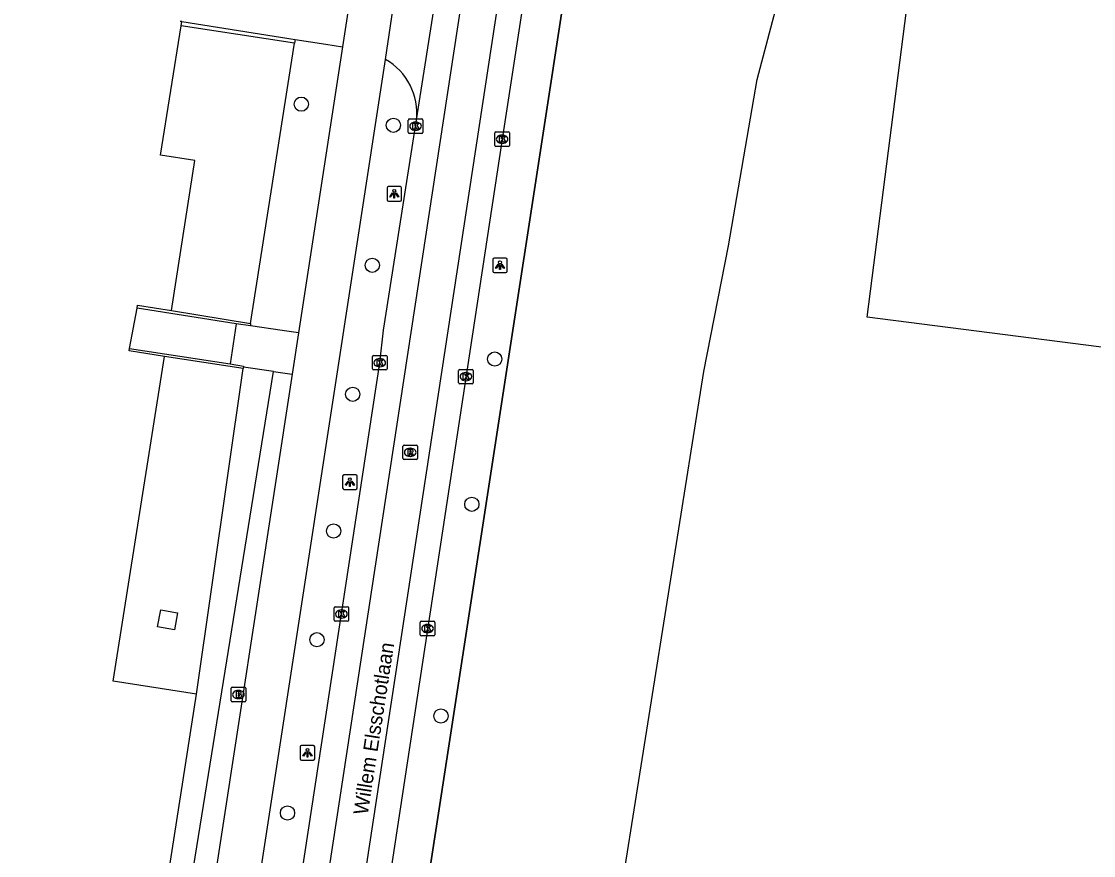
# Model space of a CAD drawing. Extents: x 161094 to 161705, y 379509 to 380907.
# Drawn here: x 161340 to 161413.8, y 380617.3 to 380674.7 of the extents above; entities that cross this region are included whole.
import ezdxf

# ---------------------------------------------------------------- set-up
doc = ezdxf.new("R2010")
doc.units = 0
for name, color, linetype in [('IMGEO_Boom', 7, 'Continuous'), ('IMGEO_Brandkraan', 7, 'Continuous'), ('IMGEO_Fietspad_gesloten', 7, 'Continuous'), ('IMGEO_Grasland_overig', 7, 'Continuous'), ('IMGEO_Groenvoorziening', 7, 'Continuous'), ('IMGEO_Haag', 7, 'Continuous'), ('IMGEO_Hek', 7, 'Continuous'), ('IMGEO_Kolk', 7, 'Continuous'), ('IMGEO_Lichtpunt', 7, 'Continuous'), ('IMGEO_Muur', 7, 'Continuous'), ('IMGEO_Openbare_ruimte_label', 7, 'Continuous'), ('IMGEO_Pand', 7, 'Continuous'), ('IMGEO_Pand_vergunning_verleend', 7, 'Continuous'), ('IMGEO_Rijbaan_lokaal_gesloten', 7, 'Continuous'), ('IMGEO_Rioolput', 7, 'Continuous'), ('IMGEO_Voetpad_open', 7, 'Continuous')]:
    doc.layers.add(name, color=color, linetype=linetype)

msp = doc.modelspace()

# ---------------------------------------------------------------- linework, layer by layer
at = {"layer": 'IMGEO_Boom'}
for centre in [(161359.244, 380668.971), (161365.582, 380667.515), (161364.131, 380657.886), (161372.554, 380651.434), (161362.782, 380649.011), (161370.978, 380641.442), (161361.467, 380639.604), (161360.319, 380632.127), (161368.856, 380626.877), (161358.295, 380620.204)]:
    msp.add_circle(centre, 0.489, dxfattribs=at)
at = {"layer": 'IMGEO_Brandkraan'}
for p, q in [((161354.415, 380627.93), (161354.415, 380628.782)), ((161354.49, 380628.856), (161355.342, 380628.856)), ((161354.903, 380628.636), (161354.928, 380628.636)), ((161355.416, 380628.782), (161355.416, 380627.93)), ((161355.342, 380627.856), (161354.49, 380627.856)), ((161354.926, 380628.076), (161354.901, 380628.076))]:
    msp.add_line(p, q, dxfattribs=at)
for points in [[(161354.415, 380627.93), (161354.415, 380628.782)], [(161354.49, 380628.856), (161355.342, 380628.856)], [(161354.763, 380628.556), (161354.763, 380628.156), (161354.976, 380628.156)], [(161354.994, 380628.556), (161354.763, 380628.556)], [(161354.942, 380628.475), (161354.888, 380628.475), (161354.888, 380628.399)], [(161354.888, 380628.399), (161354.941, 380628.399)], [(161354.95, 380628.323), (161354.888, 380628.323), (161354.888, 380628.242)], [(161354.888, 380628.242), (161354.95, 380628.242)], [(161355.416, 380628.782), (161355.416, 380627.93)], [(161355.342, 380627.856), (161354.49, 380627.856)]]:
    msp.add_lwpolyline(points, dxfattribs=at)
for centre, radius, start, end in [((161354.492, 380628.78), 0.0765, 91.55205, 178.44795), ((161354.492, 380628.78), 0.0765, 91.55205, 178.44795), ((161354.943, 380628.437), 0.0379, 267.82845, 90.93552), ((161354.951, 380628.282), 0.0404, 269.87594, 90.50774), ((161354.998, 380628.411), 0.145, 59.4692, 91.53667), ((161355.023, 380628.458), 0.0922, 285.51372, 58.15012), ((161355.028, 380628.266), 0.105, 301.31148, 78.98903), ((161355.34, 380628.78), 0.0765, 1.55205, 88.44795), ((161355.34, 380628.78), 0.0765, 1.55205, 88.44795), ((161354.492, 380627.932), 0.0765, 181.55205, 268.44795), ((161354.492, 380627.932), 0.0765, 181.55205, 268.44795), ((161354.982, 380628.407), 0.251, 268.66757, 293.53466), ((161355.34, 380627.932), 0.0765, 271.55205, 358.44795), ((161355.34, 380627.932), 0.0765, 271.55205, 358.44795)]:
    msp.add_arc(centre, radius, start, end, dxfattribs=at)
for centre, major_axis, ratio, start_param, end_param in [((161354.902, 380628.356), (-0.387, 0.002), 0.722429, 4.712389, 7.853982), ((161354.927, 380628.356), (-0.39, 0.002), 0.717154, 1.570796, 4.712389)]:
    msp.add_ellipse(centre, major_axis=major_axis, ratio=ratio, start_param=start_param, end_param=end_param, dxfattribs=at)
at = {"layer": 'IMGEO_Fietspad_gesloten'}
for points in [[(161362.964, 380678.743), (161362.07, 380672.915)], [(161365.033, 380672.035), (161366.062, 380679.022)], [(161362.07, 380672.915), (161359.052, 380653.248)], [(161347.54, 380558.203), (161365.033, 380672.035)], [(161359.052, 380653.248), (161358.615, 380650.395)], [(161358.615, 380650.395), (161352.499, 380610.536)]]:
    msp.add_lwpolyline(points, dxfattribs=at)
at = {"layer": 'IMGEO_Grasland_overig'}
msp.add_lwpolyline([(161380.532, 380610.266), (161380.816, 380612.046), (161386.952, 380650.576), (161388.642, 380659.221), (161390.629, 380670.674), (161392.829, 380679.019), (161394.81, 380684.162), (161399.827, 380694.406), (161401.55, 380696.729), (161411.895, 380689.797), (161413.736, 380691.575), (161412.517, 380710.46)], dxfattribs=at)
at = {"layer": 'IMGEO_Groenvoorziening'}
for points in [[(161405.29, 380858.44), (161376.121, 380668.459), (161366.925, 380608.735), (161353.592, 380520.726), (161347.606, 380481.216)], [(161355.744, 380653.874), (161358.768, 380673.154)], [(161350.731, 380633.977), (161350.52, 380632.797), (161349.358, 380633.011), (161349.569, 380634.173), (161350.731, 380633.977)]]:
    msp.add_lwpolyline(points, dxfattribs=at)
at = {"layer": 'IMGEO_Haag'}
for points in [[(161350.91, 380610.77), (161357.34, 380650.575)], [(161352.038, 380628.383), (161355.234, 380650.781)]]:
    msp.add_lwpolyline(points, dxfattribs=at)
at = {"layer": 'IMGEO_Hek'}
for points in [[(161376.121, 380668.459), (161405.29, 380858.44)], [(161353.592, 380520.726), (161366.925, 380608.735), (161376.121, 380668.459)]]:
    msp.add_lwpolyline(points, dxfattribs=at)
at = {"layer": 'IMGEO_Kolk'}
for p, q in [((161366.61, 380667.026), (161366.61, 380667.878)), ((161366.685, 380667.952), (161367.537, 380667.952)), ((161367.098, 380667.732), (161367.123, 380667.732)), ((161367.611, 380667.878), (161367.611, 380667.026)), ((161367.537, 380666.952), (161366.685, 380666.952)), ((161367.121, 380667.172), (161367.096, 380667.172)), ((161372.564, 380666.133), (161372.564, 380666.985)), ((161372.639, 380667.059), (161373.491, 380667.059)), ((161373.052, 380666.839), (161373.077, 380666.839)), ((161373.565, 380666.985), (161373.565, 380666.133)), ((161373.491, 380666.059), (161372.639, 380666.059)), ((161373.075, 380666.279), (161373.05, 380666.279)), ((161364.142, 380650.756), (161364.142, 380651.608)), ((161364.217, 380651.682), (161365.069, 380651.682)), ((161364.63, 380651.462), (161364.655, 380651.462)), ((161365.143, 380651.608), (161365.143, 380650.756)), ((161365.069, 380650.682), (161364.217, 380650.682)), ((161364.653, 380650.902), (161364.628, 380650.902)), ((161370.074, 380649.798), (161370.074, 380650.65)), ((161370.149, 380650.724), (161371.001, 380650.724)), ((161370.562, 380650.504), (161370.587, 380650.504)), ((161371.075, 380650.65), (161371.075, 380649.798)), ((161371.001, 380649.724), (161370.149, 380649.724)), ((161370.585, 380649.944), (161370.56, 380649.944)), ((161361.503, 380633.469), (161361.503, 380634.321)), ((161361.578, 380634.395), (161362.43, 380634.395)), ((161361.991, 380634.175), (161362.016, 380634.175)), ((161362.504, 380634.321), (161362.504, 380633.469)), ((161362.014, 380633.615), (161361.989, 380633.615)), ((161362.43, 380633.395), (161361.578, 380633.395)), ((161367.433, 380632.467), (161367.433, 380633.319)), ((161367.508, 380633.393), (161368.36, 380633.393)), ((161367.921, 380633.173), (161367.946, 380633.173)), ((161368.434, 380633.319), (161368.434, 380632.467)), ((161368.36, 380632.393), (161367.508, 380632.393)), ((161367.944, 380632.613), (161367.919, 380632.613))]:
    msp.add_line(p, q, dxfattribs=at)
for points in [[(161366.61, 380667.026), (161366.61, 380667.878)], [(161366.685, 380667.952), (161367.537, 380667.952)], [(161366.931, 380667.652), (161367.054, 380667.652), (161367.054, 380667.501), (161367.184, 380667.652), (161367.348, 380667.652), (161367.202, 380667.501), (161367.355, 380667.252), (161367.203, 380667.252), (161367.118, 380667.416), (161367.054, 380667.349), (161367.054, 380667.252), (161366.931, 380667.252), (161366.931, 380667.652)], [(161367.611, 380667.878), (161367.611, 380667.026)], [(161367.537, 380666.952), (161366.685, 380666.952)], [(161372.564, 380666.133), (161372.564, 380666.985)], [(161372.639, 380667.059), (161373.491, 380667.059)], [(161372.885, 380666.759), (161373.008, 380666.759), (161373.008, 380666.608), (161373.138, 380666.759), (161373.302, 380666.759), (161373.156, 380666.608), (161373.309, 380666.359), (161373.157, 380666.359), (161373.072, 380666.523), (161373.008, 380666.456), (161373.008, 380666.359), (161372.885, 380666.359), (161372.885, 380666.759)], [(161373.565, 380666.985), (161373.565, 380666.133)], [(161373.491, 380666.059), (161372.639, 380666.059)], [(161364.142, 380650.756), (161364.142, 380651.608)], [(161364.217, 380651.682), (161365.069, 380651.682)], [(161364.463, 380651.382), (161364.586, 380651.382), (161364.586, 380651.231), (161364.716, 380651.382), (161364.88, 380651.382), (161364.734, 380651.231), (161364.887, 380650.982), (161364.735, 380650.982), (161364.65, 380651.146), (161364.586, 380651.079), (161364.586, 380650.982), (161364.463, 380650.982), (161364.463, 380651.382)], [(161365.143, 380651.608), (161365.143, 380650.756)], [(161365.069, 380650.682), (161364.217, 380650.682)], [(161370.074, 380649.798), (161370.074, 380650.65)], [(161370.149, 380650.724), (161371.001, 380650.724)], [(161370.395, 380650.424), (161370.518, 380650.424), (161370.518, 380650.273), (161370.648, 380650.424), (161370.812, 380650.424), (161370.666, 380650.273), (161370.819, 380650.024), (161370.667, 380650.024), (161370.582, 380650.188), (161370.518, 380650.121), (161370.518, 380650.024), (161370.395, 380650.024), (161370.395, 380650.424)], [(161371.075, 380650.65), (161371.075, 380649.798)], [(161371.001, 380649.724), (161370.149, 380649.724)], [(161361.503, 380633.469), (161361.503, 380634.321)], [(161361.578, 380634.395), (161362.43, 380634.395)], [(161362.504, 380634.321), (161362.504, 380633.469)], [(161361.824, 380634.095), (161361.947, 380634.095), (161361.947, 380633.944), (161362.077, 380634.095), (161362.241, 380634.095), (161362.095, 380633.944), (161362.248, 380633.695), (161362.096, 380633.695), (161362.011, 380633.859), (161361.947, 380633.792), (161361.947, 380633.695), (161361.824, 380633.695), (161361.824, 380634.095)], [(161362.43, 380633.395), (161361.578, 380633.395)], [(161367.433, 380632.467), (161367.433, 380633.319)], [(161367.508, 380633.393), (161368.36, 380633.393)], [(161367.754, 380633.093), (161367.877, 380633.093), (161367.877, 380632.942), (161368.007, 380633.093), (161368.171, 380633.093), (161368.025, 380632.942), (161368.178, 380632.693), (161368.026, 380632.693), (161367.941, 380632.857), (161367.877, 380632.79), (161367.877, 380632.693), (161367.754, 380632.693), (161367.754, 380633.093)], [(161368.434, 380633.319), (161368.434, 380632.467)], [(161368.36, 380632.393), (161367.508, 380632.393)]]:
    msp.add_lwpolyline(points, dxfattribs=at)
for centre, start, end in [((161366.687, 380667.876), 91.55205, 178.44795), ((161366.687, 380667.876), 91.55205, 178.44795), ((161367.535, 380667.876), 1.55205, 88.44795), ((161367.535, 380667.876), 1.55205, 88.44795), ((161366.687, 380667.028), 181.55205, 268.44795), ((161366.687, 380667.028), 181.55205, 268.44795), ((161367.535, 380667.028), 271.55205, 358.44795), ((161367.535, 380667.028), 271.55205, 358.44795), ((161372.641, 380666.983), 91.55205, 178.44795), ((161372.641, 380666.983), 91.55205, 178.44795), ((161373.489, 380666.983), 1.55205, 88.44795), ((161373.489, 380666.983), 1.55205, 88.44795), ((161372.641, 380666.135), 181.55205, 268.44795), ((161372.641, 380666.135), 181.55205, 268.44795), ((161373.489, 380666.135), 271.55205, 358.44795), ((161373.489, 380666.135), 271.55205, 358.44795), ((161364.219, 380651.606), 91.55205, 178.44795), ((161364.219, 380651.606), 91.55205, 178.44795), ((161365.067, 380651.606), 1.55205, 88.44795), ((161365.067, 380651.606), 1.55205, 88.44795), ((161364.219, 380650.758), 181.55205, 268.44795), ((161364.219, 380650.758), 181.55205, 268.44795), ((161365.067, 380650.758), 271.55205, 358.44795), ((161365.067, 380650.758), 271.55205, 358.44795), ((161370.151, 380650.648), 91.55205, 178.44795), ((161370.151, 380650.648), 91.55205, 178.44795), ((161370.999, 380650.648), 1.55205, 88.44795), ((161370.999, 380650.648), 1.55205, 88.44795), ((161370.151, 380649.8), 181.55205, 268.44795), ((161370.151, 380649.8), 181.55205, 268.44795), ((161370.999, 380649.8), 271.55205, 358.44795), ((161370.999, 380649.8), 271.55205, 358.44795), ((161361.58, 380634.319), 91.55205, 178.44795), ((161361.58, 380634.319), 91.55205, 178.44795), ((161362.428, 380634.319), 1.55205, 88.44795), ((161362.428, 380634.319), 1.55205, 88.44795), ((161361.58, 380633.471), 181.55205, 268.44795), ((161361.58, 380633.471), 181.55205, 268.44795), ((161362.428, 380633.471), 271.55205, 358.44795), ((161362.428, 380633.471), 271.55205, 358.44795), ((161367.51, 380633.317), 91.55205, 178.44795), ((161367.51, 380633.317), 91.55205, 178.44795), ((161368.358, 380633.317), 1.55205, 88.44795), ((161368.358, 380633.317), 1.55205, 88.44795), ((161367.51, 380632.469), 181.55205, 268.44795), ((161367.51, 380632.469), 181.55205, 268.44795), ((161368.358, 380632.469), 271.55205, 358.44795), ((161368.358, 380632.469), 271.55205, 358.44795)]:
    msp.add_arc(centre, 0.0765, start, end, dxfattribs=at)
for centre, major_axis, ratio, start_param, end_param in [((161367.097, 380667.452), (-0.387, 0.002), 0.722429, 4.712389, 7.853982), ((161367.122, 380667.452), (-0.39, 0.002), 0.717154, 1.570796, 4.712389), ((161373.051, 380666.559), (-0.387, 0.002), 0.722429, 4.712389, 7.853982), ((161373.076, 380666.559), (-0.39, 0.002), 0.717154, 1.570796, 4.712389), ((161364.629, 380651.182), (-0.387, 0.002), 0.722429, 4.712389, 7.853982), ((161364.654, 380651.182), (-0.39, 0.002), 0.717154, 1.570796, 4.712389), ((161370.561, 380650.224), (-0.387, 0.002), 0.722429, 4.712389, 7.853982), ((161370.586, 380650.224), (-0.39, 0.002), 0.717154, 1.570796, 4.712389), ((161361.99, 380633.895), (-0.387, 0.002), 0.722429, 4.712389, 7.853982), ((161362.015, 380633.895), (-0.39, 0.002), 0.717154, 1.570796, 4.712389), ((161367.92, 380632.893), (-0.387, 0.002), 0.722429, 4.712389, 7.853982), ((161367.945, 380632.893), (-0.39, 0.002), 0.717154, 1.570796, 4.712389)]:
    msp.add_ellipse(centre, major_axis=major_axis, ratio=ratio, start_param=start_param, end_param=end_param, dxfattribs=at)
at = {"layer": 'IMGEO_Lichtpunt'}
for p, q in [((161365.144, 380663.201), (161365.144, 380662.394)), ((161365.144, 380663.201), (161365.144, 380662.394)), ((161366.046, 380663.296), (161365.238, 380663.296)), ((161366.046, 380663.296), (161365.238, 380663.296)), ((161366.14, 380662.394), (161366.14, 380663.201)), ((161366.14, 380662.394), (161366.14, 380663.201)), ((161365.238, 380662.3), (161366.046, 380662.3)), ((161365.238, 380662.3), (161366.046, 380662.3)), ((161372.42, 380658.29), (161372.42, 380657.483)), ((161372.42, 380658.29), (161372.42, 380657.483)), ((161373.322, 380658.385), (161372.514, 380658.385)), ((161373.322, 380658.385), (161372.514, 380658.385)), ((161373.416, 380657.483), (161373.416, 380658.29)), ((161373.416, 380657.483), (161373.416, 380658.29)), ((161372.514, 380657.389), (161373.322, 380657.389)), ((161372.514, 380657.389), (161373.322, 380657.389)), ((161362.088, 380643.372), (161362.088, 380642.565)), ((161362.088, 380643.372), (161362.088, 380642.565)), ((161362.99, 380643.467), (161362.182, 380643.467)), ((161362.99, 380643.467), (161362.182, 380643.467)), ((161363.084, 380642.565), (161363.084, 380643.372)), ((161363.084, 380642.565), (161363.084, 380643.372)), ((161362.182, 380642.471), (161362.99, 380642.471)), ((161362.182, 380642.471), (161362.99, 380642.471)), ((161359.172, 380624.748), (161359.172, 380623.941)), ((161359.172, 380624.748), (161359.172, 380623.941)), ((161360.074, 380624.843), (161359.266, 380624.843)), ((161360.074, 380624.843), (161359.266, 380624.843)), ((161360.168, 380623.941), (161360.168, 380624.748)), ((161360.168, 380623.941), (161360.168, 380624.748)), ((161359.266, 380623.847), (161360.074, 380623.847)), ((161359.266, 380623.847), (161360.074, 380623.847))]:
    msp.add_line(p, q, dxfattribs=at)
for points in [[(161365.518, 380662.865), (161365.557, 380662.837), (161365.369, 380662.575), (161365.331, 380662.602), (161365.518, 380662.865)], [(161365.62, 380662.817), (161365.667, 380662.817), (161365.667, 380662.495), (161365.62, 380662.495), (161365.62, 380662.817)], [(161365.73, 380662.837), (161365.768, 380662.864), (161365.955, 380662.602), (161365.916, 380662.574), (161365.73, 380662.837)], [(161372.794, 380657.954), (161372.833, 380657.926), (161372.645, 380657.664), (161372.607, 380657.691), (161372.794, 380657.954)], [(161372.896, 380657.906), (161372.943, 380657.906), (161372.943, 380657.584), (161372.896, 380657.584), (161372.896, 380657.906)], [(161373.006, 380657.926), (161373.044, 380657.953), (161373.231, 380657.691), (161373.192, 380657.663), (161373.006, 380657.926)], [(161362.462, 380643.036), (161362.501, 380643.008), (161362.313, 380642.746), (161362.275, 380642.773), (161362.462, 380643.036)], [(161362.674, 380643.008), (161362.712, 380643.035), (161362.899, 380642.773), (161362.86, 380642.745), (161362.674, 380643.008)], [(161362.564, 380642.988), (161362.611, 380642.988), (161362.611, 380642.666), (161362.564, 380642.666), (161362.564, 380642.988)], [(161359.546, 380624.412), (161359.585, 380624.384), (161359.397, 380624.122), (161359.359, 380624.149), (161359.546, 380624.412)], [(161359.648, 380624.364), (161359.695, 380624.364), (161359.695, 380624.042), (161359.648, 380624.042), (161359.648, 380624.364)], [(161359.758, 380624.384), (161359.796, 380624.411), (161359.983, 380624.149), (161359.944, 380624.121), (161359.758, 380624.384)]]:
    msp.add_lwpolyline(points, dxfattribs=at)
for centre in [(161365.643, 380662.999), (161372.919, 380658.088), (161362.587, 380643.17), (161359.671, 380624.546)]:
    msp.add_circle(centre, 0.0994, dxfattribs=at)
for centre, start, end in [((161365.238, 380663.201), 90, 180), ((161365.238, 380663.201), 90, 180), ((161366.046, 380663.201), 0, 90), ((161366.046, 380663.201), 0, 90), ((161365.238, 380662.394), 180, 270), ((161365.238, 380662.394), 180, 270), ((161366.046, 380662.394), 270, 0), ((161366.046, 380662.394), 270, 360), ((161372.514, 380658.29), 90, 180), ((161372.514, 380658.29), 90, 180), ((161373.322, 380658.29), 0, 90), ((161373.322, 380658.29), 0, 90), ((161372.514, 380657.483), 180, 270), ((161372.514, 380657.483), 180, 270), ((161373.322, 380657.483), 270, 0), ((161373.322, 380657.483), 270, 360), ((161362.182, 380643.372), 90, 180), ((161362.182, 380643.372), 90, 180), ((161362.99, 380643.372), 0, 90), ((161362.99, 380643.372), 0, 90), ((161362.182, 380642.565), 180, 270), ((161362.182, 380642.565), 180, 270), ((161362.99, 380642.565), 270, 0), ((161362.99, 380642.565), 270, 360), ((161359.266, 380624.748), 90, 180), ((161359.266, 380624.748), 90, 180), ((161360.074, 380624.748), 0, 90), ((161360.074, 380624.748), 0, 90), ((161359.266, 380623.941), 180, 270), ((161359.266, 380623.941), 180, 270), ((161360.074, 380623.941), 270, 0), ((161360.074, 380623.941), 270, 360)]:
    msp.add_arc(centre, 0.0946, start, end, dxfattribs=at)
at = {"layer": 'IMGEO_Muur'}
for points in [[(161358.768, 380673.154), (161350.974, 380674.355)], [(161351.021, 380674.65), (161358.821, 380673.421)], [(161358.821, 380673.421), (161358.768, 380673.154)], [(161354.752, 380653.867), (161347.94, 380654.933)], [(161350.309, 380654.767), (161355.744, 380653.874)], [(161355.744, 380653.715), (161354.752, 380653.867)], [(161355.744, 380653.874), (161355.744, 380653.715)], [(161347.42, 380652.158), (161354.34, 380651.099)], [(161355.234, 380650.781), (161349.821, 380651.619)], [(161354.34, 380651.099), (161355.271, 380650.933), (161355.268, 380650.867)], [(161355.268, 380650.867), (161355.234, 380650.781)]]:
    msp.add_lwpolyline(points, dxfattribs=at)
at = {"layer": 'IMGEO_Pand'}
for points in [[(161350.309, 380654.767), (161351.908, 380665.091), (161349.549, 380665.469), (161350.974, 380674.355)], [(161351.021, 380674.65), (161350.918, 380674.666)], [(161350.974, 380674.355), (161351.021, 380674.65)], [(161347.42, 380652.158), (161347.94, 380654.933)], [(161347.94, 380654.933), (161347.981, 380655.15), (161350.309, 380654.767)], [(161349.821, 380651.619), (161347.389, 380651.995), (161347.42, 380652.158)], [(161352.038, 380628.383), (161346.301, 380629.278), (161349.821, 380651.619)], [(161349.332, 380611.003), (161352.038, 380628.383)]]:
    msp.add_lwpolyline(points, dxfattribs=at)
at = {"layer": 'IMGEO_Pand_vergunning_verleend'}
msp.add_lwpolyline([(161398.18, 380654.32), (161402.454, 380687.597), (161464.781, 380678.671), (161460.613, 380646.22), (161432.685, 380649.806), (161433.004, 380652.29), (161426.809, 380653.085), (161426.501, 380650.683), (161398.18, 380654.32)], dxfattribs=at)
at = {"layer": 'IMGEO_Rijbaan_lokaal_gesloten'}
for points in [[(161339.984, 380477.773), (161375.194, 380708.235), (161388.922, 380797.51), (161396.234, 380843.996), (161396.663, 380846.991)], [(161399.153, 380846.596), (161398.722, 380843.492), (161391.386, 380797.079), (161377.702, 380708.239), (161342.463, 380477.394)], [(161400.962, 380846.207), (161400.622, 380844.851), (161395.87, 380814.342), (161392.957, 380796.042), (161379.164, 380706.261), (161373.065, 380666.559), (161354.682, 380545.949), (161344.875, 380482.113)], [(161367.178, 380667.879), (161369.527, 380682.914)], [(161351.073, 380562.281), (161364.643, 380651.182), (161364.91, 380653.432), (161367.178, 380667.879)]]:
    msp.add_lwpolyline(points, dxfattribs=at)
at = {"layer": 'IMGEO_Rioolput'}
for p, q in [((161366.243, 380644.588), (161366.243, 380645.44)), ((161366.318, 380645.514), (161367.17, 380645.514)), ((161366.731, 380645.294), (161366.756, 380645.294)), ((161367.244, 380645.44), (161367.244, 380644.588)), ((161367.17, 380644.514), (161366.318, 380644.514)), ((161366.754, 380644.734), (161366.729, 380644.734))]:
    msp.add_line(p, q, dxfattribs=at)
for points in [[(161366.243, 380644.588), (161366.243, 380645.44)], [(161366.318, 380645.514), (161367.17, 380645.514)], [(161366.832, 380645.212), (161366.58, 380645.214), (161366.58, 380644.814)], [(161367.244, 380645.44), (161367.244, 380644.588)], [(161367.17, 380644.514), (161366.318, 380644.514)], [(161366.58, 380644.814), (161366.704, 380644.814), (161366.704, 380644.976), (161366.715, 380644.976)], [(161366.758, 380645.133), (161366.704, 380645.133), (161366.704, 380645.052)], [(161366.704, 380645.052), (161366.756, 380645.052)], [(161366.762, 380644.947), (161366.833, 380644.814), (161366.973, 380644.814), (161366.908, 380644.94)]]:
    msp.add_lwpolyline(points, dxfattribs=at)
for centre, radius, start, end in [((161366.32, 380645.438), 0.0765, 91.55205, 178.44795), ((161366.32, 380645.438), 0.0765, 91.55205, 178.44795), ((161366.831, 380645.102), 0.109, 350.36119, 89.41601), ((161367.168, 380645.438), 0.0765, 1.55205, 88.44795), ((161367.168, 380645.438), 0.0765, 1.55205, 88.44795), ((161366.32, 380644.59), 0.0765, 181.55205, 268.44795), ((161366.32, 380644.59), 0.0765, 181.55205, 268.44795), ((161366.714, 380644.923), 0.0533, 26.02933, 88.69889), ((161366.74, 380645.241), 0.19, 274.7715, 282.96867), ((161366.764, 380645.037), 0.0964, 77.00612, 93.18647), ((161366.778, 380645.094), 0.0378, 276.66336, 79.67722), ((161366.829, 380645.102), 0.112, 277.58423, 350.98172), ((161366.813, 380644.887), 0.108, 29.51342, 73.79051), ((161367.168, 380644.59), 0.0765, 271.55205, 358.44795), ((161367.168, 380644.59), 0.0765, 271.55205, 358.44795)]:
    msp.add_arc(centre, radius, start, end, dxfattribs=at)
for centre, major_axis, ratio, start_param, end_param in [((161366.73, 380645.014), (-0.387, 0.002), 0.722429, 4.712389, 7.853982), ((161366.755, 380645.014), (-0.39, 0.002), 0.717154, 1.570796, 4.712389)]:
    msp.add_ellipse(centre, major_axis=major_axis, ratio=ratio, start_param=start_param, end_param=end_param, dxfattribs=at)
at = {"layer": 'IMGEO_Voetpad_open'}
for points in [[(161358.821, 380673.421), (161360.934, 380673.092), (161362.07, 380672.915)], [(161354.752, 380653.867), (161354.34, 380651.099)], [(161359.052, 380653.248), (161357.919, 380653.408), (161355.744, 380653.715)], [(161357.34, 380650.575), (161355.268, 380650.867)], [(161357.34, 380650.575), (161358.615, 380650.395)]]:
    msp.add_lwpolyline(points, dxfattribs=at)
msp.add_arc((161362.96, 380668.333), 4.243, 353.85164, 60.7468, dxfattribs=at)

# ---------------------------------------------------------------- texts
at = {"layer": 'IMGEO_Openbare_ruimte_label'}
msp.add_text('Willem Elsschotlaan', height=1, rotation=81.1972, dxfattribs=at).set_placement((161363.812, 380620.031))

doc.saveas('drawing.dxf')
